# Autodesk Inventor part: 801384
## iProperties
IsCustomPart: 0
Created: 2007-03
Part Number: 801384
Material: Steel, High Strength Low Alloy
Description: AS 1427 - M3 X 6
Document SubType Name: Modeling
Standard: AS 1427
Designer: JJ
Standards Organization: AS
Language: en-US
Size Designation: M3 x 6
Categories: <MemberInstance><Categories><Category DisplayName="Fasteners" InternalName="e4da775c-781d-43d5-af7c-5136215cf5a6" Mnemonic="FSTN"><Category DisplayName="Bolts"
Density: 7.84 g/cm^3
Mass: 0.76575 g
Surface Area: 1.6834 cm^2
Volume: 0.0976721 cm^3
Component Category: Fasteners
Author: JJ
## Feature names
1. Body [Revolution]
2. Head [Extrusion]
3. Chamfer1 [Revolution]
4. Chamfer2
